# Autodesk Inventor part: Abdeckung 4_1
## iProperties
Shininess: 64.0
Length Units: 11269
Angle Units: 11279
Time Units: 11290
Mass Units: 11283
Length Display Precision: 3
Angle Display Precision: 2
Compacted: True
Part Number: Abdeckung 4_1
Document SubType Name: Sheet Metal
Created: 2005-02
Material: Nichtrostender Stahl (austenitisch)
Designer: Administrator
Manufacturer: Standard
Standards Organization: Custom
Cost Center: 4,5 kg
Density: 0.0
Volumn: 0.0
Area: 0.0
PropertySet Name: Model Information
Control State: 0
Master: False
Checked Out: False
SaveDate: 2005-02-17
SaveTime: 07:41
TotalMass: 4,5 kg
SM_Thickness: 1,5 mm
SM_Style: Standard
SM_Extents: 289,572 mm x 1524,848 mm
SM_Extents_Width: 289,572 mm
SM_Extents_Length: 1524,848 mm
Author: Administrator
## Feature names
1. Platte1
2. Platte2
3. Biegung1
4. Platte3
5. Biegung2
6. Platte4
7. Biegung3
8. Platte5
9. Biegung4
10. Platte6
11. Biegung5
12. Platte7
13. Biegung6
14. Platte8
15. Biegung7
16. Platte9
17. Biegung8
18. ExtrusionAbwicklung1
19. Ecke1
20. Ecke2
21. Ecke3
22. Ecke4
23. Ausklinkung1
24. Ecke10
25. Ecke11
26. Ecke12
27. Ecke13
28. Ausschneiden4
29. Ausschneiden5
30. Ecke8
